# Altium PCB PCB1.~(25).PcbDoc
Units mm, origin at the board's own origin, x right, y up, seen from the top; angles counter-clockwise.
Board outline 32.13 x 39.5 mm, 2 copper layers (Top Layer, Bottom Layer); 17 components, 6 nets, 43 pads, 1 vias.
Unrouted connection lines stored in the file: 15.
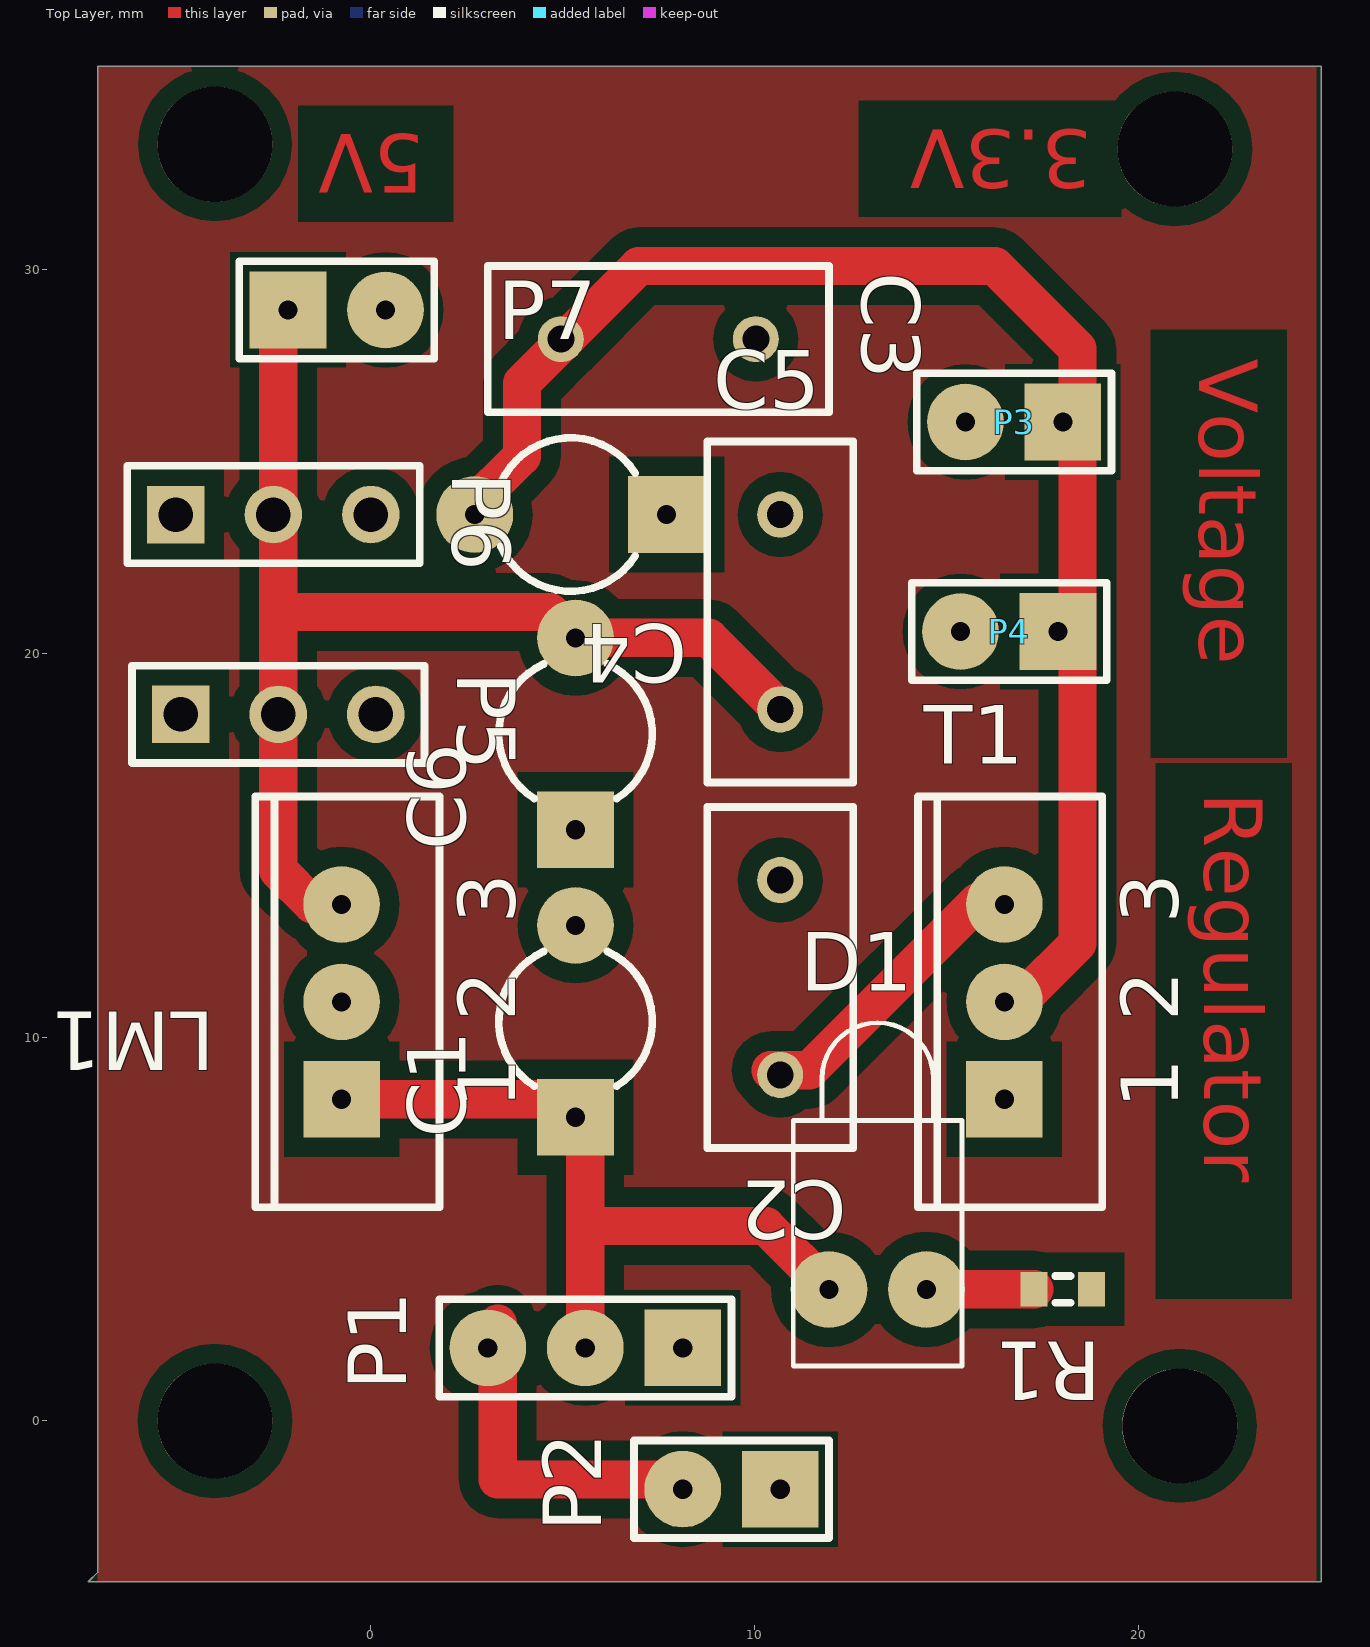
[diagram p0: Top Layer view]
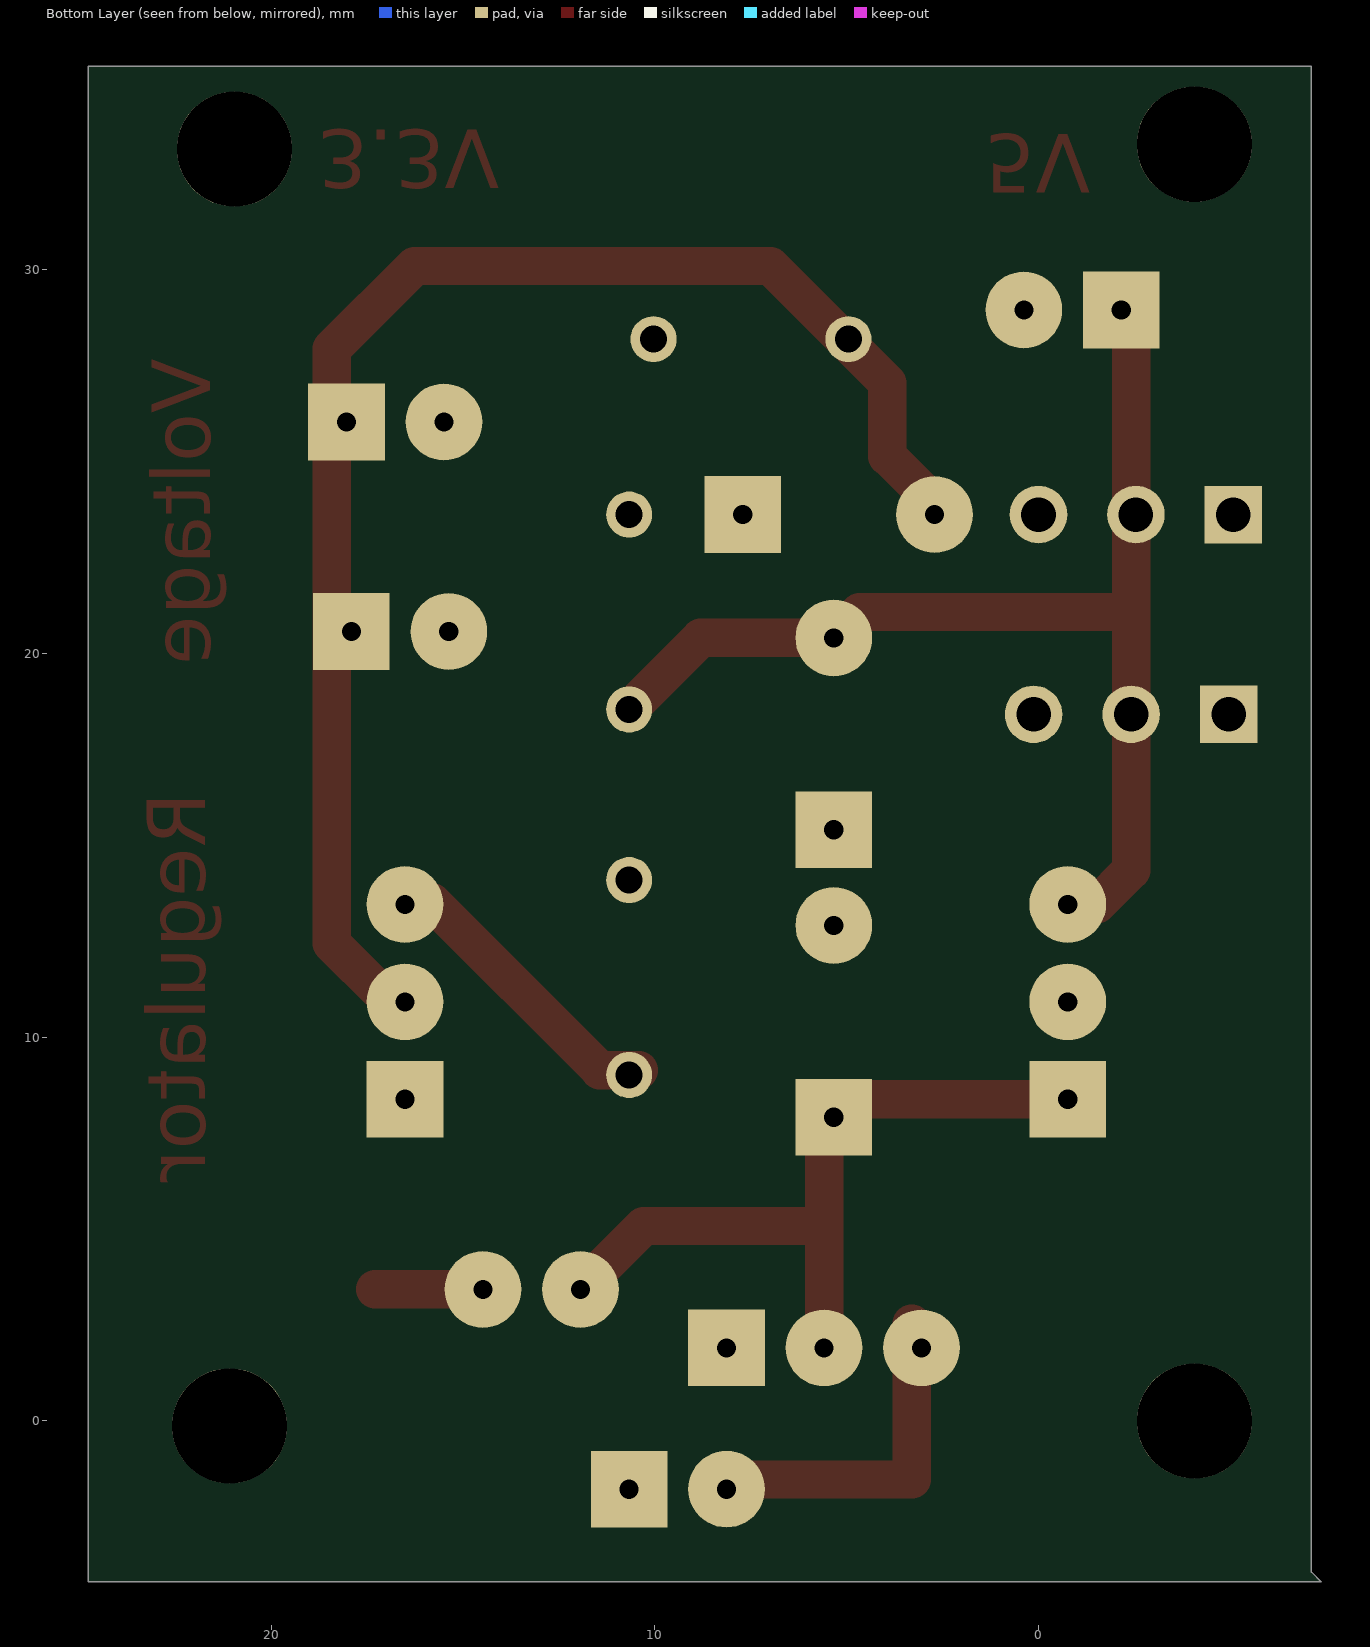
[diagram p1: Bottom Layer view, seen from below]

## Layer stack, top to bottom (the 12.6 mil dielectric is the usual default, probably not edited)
Top Layer: signal copper 0.0356
Dielectric: dielectric 0.32, FR-4, Dk 4.8
Bottom Layer: signal copper 0.0356

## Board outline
24.765,-4.191 24.765,35.306 -7.112,35.306 -7.112,-3.937 -7.366,-4.191

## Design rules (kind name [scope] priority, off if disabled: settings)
Clearance [All] p1: gap=0.5
PlaneClearance [All] p1: clearance=2
PolygonConnect [All] p1: connectstyle=Relief reliefconductorwidth=0.5 reliefentries=4 polygonreliefangle="90 Angle"
RoomDefinition Sheet1 [InComponentClass('Sheet1')] p1: confinementstyle=ConfineIn formatcopy=TRUE lockcomponents=FALSE outline -115.443,-79.248 -64.643,-79.248 -64.643,-53.848 -115.443,-53.848
RoutingVias [All] p1: holewidth=0.711 width=1.27 viastyle="Through Hole" minholewidth=0.711 minwidth=1.27 maxholewidth=0.711 maxwidth=1.27
SilkscreenOverComponentPads [All] p1: minsilkscreentomaskgap=0.254
SolderMaskExpansion [All] p1: expansion=0.102
Width [All] p1: maxlimit=1 minlimit=0.5 preferedwidth=0.5
26 further rules are at their usual default settings.

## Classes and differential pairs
component class Sheet1: C1 C2 C3 C4 C5 C6 D1 LM1 P1 P2 P3 P4 P5 P7 R1 T1

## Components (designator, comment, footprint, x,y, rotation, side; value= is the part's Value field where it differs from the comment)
C1 "Cap2" CAPR5-4X5 5.334,10.414 r90 top
C2 "Cap" RAD-0.2 10.668,11.557 r270 top
C3 "Cap" RAD-0.2 7.493,28.194 r0 top
C4 "Cap2" CAPR5-4X5 5.207,23.622 r180 top
C5 "Cap" RAD-0.2 10.668,21.082 r90 top
C6 "Cap2" CAPR5-4X5 5.334,17.907 r90 top
D1 "LED1" LED-1 13.208,3.429 r90 top
LM1 "7805" TO-220-AB -0.762,10.922 r90 top locked
P1 "Switch" HDR1X3#1 8.128,1.905 r180 top
P2 "Header 2" HDR1X2 10.668,-1.778 r180 top
P3 "Header 2" HDR1X2 18.034,26.035 r180 top
P4 "Header 2" HDR1X2 17.907,20.574 r180 top
P5 "Header 3" HDR1X3#2 -4.953,18.415 r0 top
P6 "Header 3" HDR1X3#2 -5.08,23.622 r0 top
P7 "Header 2" HDR1X2 -2.159,28.956 r0 top
R1 "Res3" J1-0603 18.034,3.429 r180 top locked
T1 "LM1117" TO-220-AB 16.51,10.922 r90 top locked

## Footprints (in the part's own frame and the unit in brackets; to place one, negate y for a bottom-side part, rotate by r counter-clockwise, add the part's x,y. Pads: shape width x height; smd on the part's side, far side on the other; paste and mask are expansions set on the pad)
CAPR5-4X5 [mm] "Capacitor; 2 Leads"
  rect 2x2 hole 0.5: 1(-2.5,0)
  round 2 hole 0.5: 2(2.5,0)
  silkscreen extent -1.69,-2 1.82,2
HDR1X2 [mm] "Connector; Header; 2 Position"
  rect 2x2 hole 0.5: 1(0,0)
  round 2 hole 0.5: 2(2.54,0)
  silkscreen extent -1.27,-1.27 3.81,1.27
HDR1X3#1 [mm] "Connector; Header; 3 Position"
  rect 2x2 hole 0.5: 1(0,0)
  round 2 hole 0.5: 2(2.54,0) 3(5.08,0)
  silkscreen extent -1.27,-1.27 6.35,1.27
HDR1X3#2 [mm] "Connector; Header; 3 Position"
  rect 1.5x1.5 hole 0.9: 1(0,0)
  round 1.5 hole 0.9: 2(2.54,0) 3(5.08,0)
  silkscreen extent -1.27,-1.27 6.35,1.27
J1-0603 [mm] "Chip Resistor, Body 1.6x0.8mm, IPC High Density"
  rect 0.7x0.9 smd: 1(-0.75,0) 2(0.75,0)
  silkscreen extent -0.2,-0.35 0.2,0.35, body extent -0.85,-0.48 0.85,0.48, height 0.9
LED-1 [mm] "LED; 2 Leads"
  round 2 hole 0.5: 1(0,1.27) 2(0,-1.27)
  silkscreen extent -2,-2.2 6.95,2.2
RAD-0.2 [mm] "Radial Cap, Thru-Hole; 2 Leads; 0.2 in Pin Spacing"
  round 1.2 hole 0.7: 1(-2.54,0) 2(2.54,0)
  silkscreen extent -4.44,-1.91 4.44,1.91
TO-220-AB [mm] "TO, Thru-Hole, Vertical, Heatsink Mounted; 3 In-Line Leads; Pitch 2.54 mm"
  rect 2x2 hole 0.5: 1(-2.54,0)
  round 2 hole 0.5: 2(0,0) 3(2.54,0)
  silkscreen extent -5.35,-2.55 5.35,2.25

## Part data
C1 C2 C3 C4 C5 C6: "Capacitor"
D1: "Typical RED GaAs LED"
LM1 T1: library part 2N3906, "PNP General Purpose Amplifier"
P1: library part "Header 3", "Header, 3-Pin"
P2 P3 P4 P7: "Header, 2-Pin"
P5 P6: "Header, 3-Pin"
R1: "Resistor"

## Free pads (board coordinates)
  round 3 hole 3: 0(-4.064,0) 0(-4.064,33.274) 0(20.955,33.147) 0(21.082,-0.127)

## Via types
v1: diameter 3, hole 2, Top Layer to Bottom Layer, 1 vias

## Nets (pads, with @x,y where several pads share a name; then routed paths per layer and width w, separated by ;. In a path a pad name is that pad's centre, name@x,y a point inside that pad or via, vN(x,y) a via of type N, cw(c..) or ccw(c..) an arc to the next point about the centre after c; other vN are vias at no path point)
GND: C1.2 C2.1 C3.2 C4.1 C5.2 C6.1 LM1.2 P2.1 P3.2 P4.2 P5.3 P6.3 P7.2 R1.1 T1.1
NetC1_1: C1.1 C2.2 D1.1 LM1.1 P1.2 T1.3 | length 25.9
  Top Layer w1: LM1.1 4.659,8.382 5.588,7.453 5.588,5.08 ; P1.2@5.588,2.54 5.588,5.08 ; C2.2@10.414,9.144 11.43,9.144 T1.3@15.811,13.525 ; D1.1 10.287,5.08 5.588,5.08
NetC3_1: C3.1 C4.2 P3.1 P4.1 T1.2 | length 38.7
  Top Layer w1: C4.2@2.54,23.749 3.937,25.146 3.937,27.051 6.985,30.099 16.256,30.099 18.415,27.94 18.415,12.446 17.081,11.112 T1.2@16.319,11.112
NetC5_1: C5.1 C6.2 LM1.3 P5.2 P6.2 P7.1 | length 30.8
  Top Layer w1: -2.413,21.082 4.659,21.082 C6.2 8.803,20.407 C5.1 ; P7.1@-2.413,28.956 -2.413,14.351 -1.524,13.462 LM1.3
NetD1_2: D1.2 R1.2 | length 2.7
  Top Layer w1: D1.2@14.577,3.429 R1.2
NetP1_3: P1.3 P2.2 | length 8.9
  Top Layer w1: P1.3@3.302,2.54 3.302,-1.524 P2.2@8.128,-1.524
pads on no net: P1.1 P5.1 P6.1
copper on no net: | length 120.4
  Top Layer w0.4: 66.741,5.898 68.291,7.448 71.291,7.448 72.591,6.148
  Bottom Layer w0.254: 72.491,58.138 72.491,6.148 77.203,6.148 ; 72.491,58.148 v1(77.191,58.148) 77.191,6.148

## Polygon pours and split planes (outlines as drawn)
no net on Top Layer "Top Layer-No Net" (solid, pour order 3): -7.112,35.306 24.638,35.306 24.638,-4.318 24.511,-4.191 -7.112,-4.191

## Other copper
Top Layer:
  text "3.3V" at 18.796,33.655 h1.52 r180
  text "5V" at 1.397,33.528 h1.52 r180
  text "Voltage" at 21.59,27.686 h1.52 r270
  text "Regulator" at 21.717,16.383 h1.52 r270

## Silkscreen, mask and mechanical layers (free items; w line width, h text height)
Mechanical 1:
  lines w0.254: -11.293,-2.41 -10.79,-3.935 ; -11.176,33.404 -10.663,34.927 ; -11.044,-3.935 -10.536,-3.936 ; -10.917,34.927 -10.409,34.926 ; -10.753,7.472 -10.79,-3.935 ; -10.7,23.52 -10.663,34.927 ; -10.277,-2.413 -10.79,-3.935 ; -10.16,33.401 -10.663,34.927 ; -4.305,46.445 -4.301,45.937 ; -2.783,46.712 -4.303,46.191 ; -2.775,45.696 -4.303,46.191 ; 2.786,46.251 -4.303,46.191 ; 18.834,46.386 25.923,46.445 ; 24.395,46.941 25.923,46.445 ; 24.403,45.925 25.923,46.445 ; 25.921,46.699 25.925,46.191
  text "30.227 (mm)" at 3.048,45.339 h1.52 r0.48
  text "38.862 (mm)" at -9.838,7.723 h1.52 r89.81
